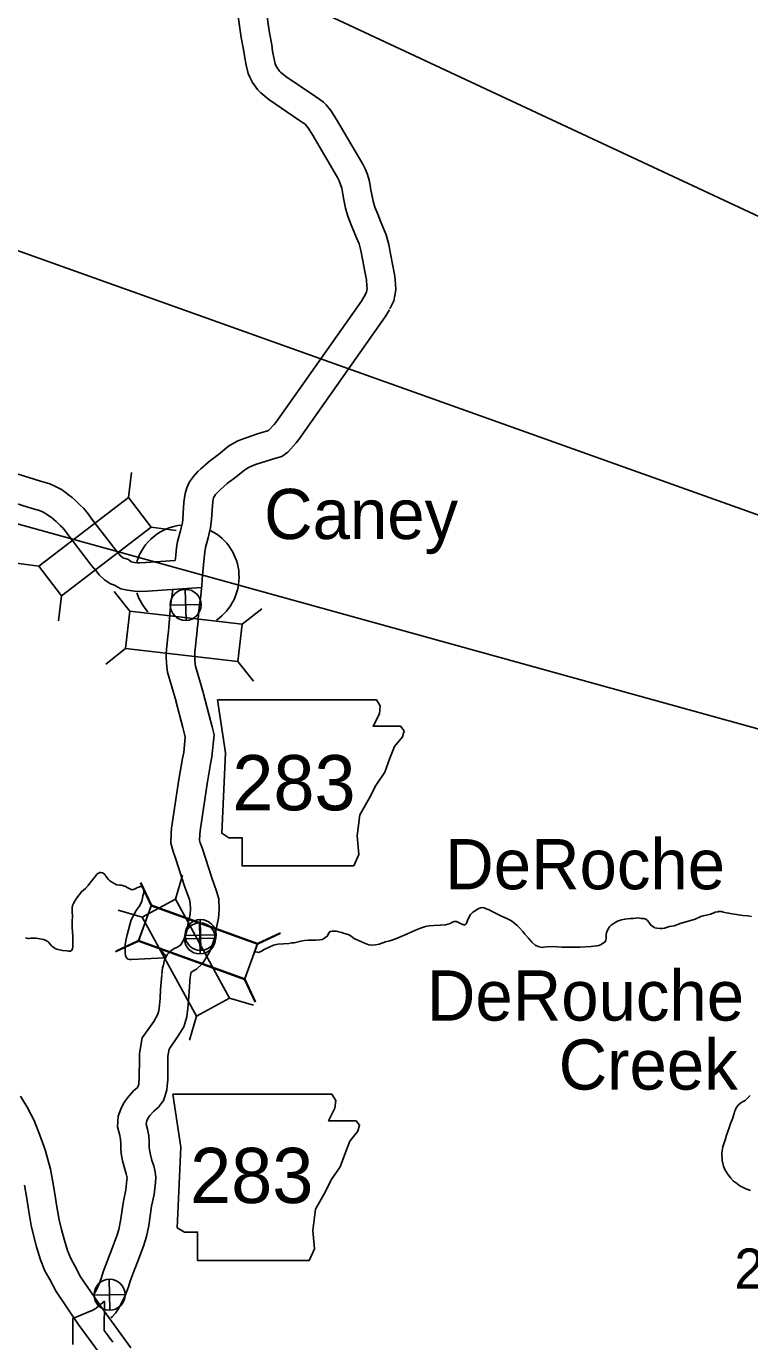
# Model space of a CAD drawing. Extents: x 1373862 to 1377080, y 1164775 to 1170415.
# Drawn here: x 1374281 to 1374357.1, y 1170012.7 to 1170151.1 of the extents above; entities that cross this region are included whole.
import ezdxf

# ---------------------------------------------------------------- set-up
doc = ezdxf.new("R2010")
doc.units = 0
doc.layers.add('1', color=7, linetype='Continuous')
doc.layers.add('Default', color=7, linetype='Continuous')

msp = doc.modelspace()

# ---------------------------------------------------------------- linework, layer by layer
at = {"layer": '1'}
for p in [(1374155.09, 1170226.04), (1374172.84, 1170165.77), (1374199.55, 1170121.07)]:
    msp.add_line(p, (1374640.76, 1169998.76), dxfattribs=at)
at = {"layer": 'Default'}
for p, q in [((1374291.74, 1170101.53), (1374292.08, 1170104.15)), ((1374294.15, 1170098.39), (1374296.77, 1170098.05)), ((1374282.31, 1170094.3), (1374279.7, 1170094.64)), ((1374297.8, 1170088.59), (1374297.72, 1170091.84)), ((1374284.72, 1170091.16), (1374284.38, 1170088.54)), ((1374291.9, 1170089.55), (1374290.26, 1170091.62)), ((1374296.13, 1170090.18), (1374299.39, 1170090.25)), ((1374303.7, 1170088.17), (1374305.77, 1170089.81)), ((1374291.44, 1170085.62), (1374289.37, 1170083.98)), ((1374303.24, 1170084.24), (1374304.88, 1170082.17)), ((1374296.68, 1170059.26), (1374297.42, 1170061.79)), ((1374294.14, 1170058.56), (1374293.02, 1170060.95)), ((1374294.16, 1170058.62), (1374293.04, 1170061.01)), ((1374296.68, 1170059.26), (1374293.2, 1170057.36)), ((1374302.38, 1170048.84), (1374296.68, 1170059.26)), ((1374293.2, 1170057.36), (1374290.67, 1170058.1)), ((1374293.2, 1170057.36), (1374298.9, 1170046.94)), ((1374299.3, 1170053.5), (1374299.23, 1170056.75)), ((1374299.37, 1170053.85), (1374299.29, 1170057.1)), ((1374292.79, 1170054.84), (1374290.4, 1170053.72)), ((1374292.81, 1170054.89), (1374290.42, 1170053.77)), ((1374297.64, 1170055.09), (1374300.89, 1170055.16)), ((1374297.7, 1170055.44), (1374300.96, 1170055.51)), ((1374305.31, 1170054.51), (1374307.7, 1170055.63)), ((1374305.33, 1170054.57), (1374307.72, 1170055.69)), ((1374303.96, 1170050.79), (1374305.08, 1170048.4)), ((1374303.98, 1170050.85), (1374305.1, 1170048.45)), ((1374298.9, 1170046.94), (1374302.38, 1170048.84)), ((1374302.38, 1170048.84), (1374304.91, 1170048.09)), ((1374298.9, 1170046.94), (1374298.16, 1170044.4)), ((1374289.8, 1170016), (1374289.72, 1170019.25)), ((1374288.13, 1170017.59), (1374291.39, 1170017.66))]:
    msp.add_line(p, q, dxfattribs=at)
for points in [[(1374305.59, 1170157.09), (1374306.57, 1170150.41), (1374306.81, 1170149.13), (1374306.9, 1170148.48), (1374307.06, 1170147.64), (1374307.19, 1170147.13), (1374307.25, 1170146.98), (1374307.38, 1170146.71), (1374307.63, 1170146.36), (1374307.72, 1170146.27), (1374308.29, 1170145.8), (1374311.4, 1170143.7), (1374311.86, 1170143.4), (1374312.27, 1170143.11), (1374312.54, 1170142.82), (1374313.03, 1170142.25), (1374313.64, 1170141.29), (1374316.4, 1170136.58), (1374316.67, 1170136.01), (1374316.87, 1170135.49), (1374317.07, 1170134.89), (1374317.18, 1170134.38), (1374317.25, 1170133.87), (1374317.33, 1170133.4), (1374317.49, 1170132.69), (1374317.66, 1170132.07), (1374317.96, 1170131.33), (1374318.25, 1170130.6), (1374318.51, 1170130), (1374318.85, 1170129.14), (1374319.13, 1170128.15), (1374319.3, 1170127.14), (1374319.54, 1170125.89), (1374319.76, 1170124.82), (1374319.82, 1170123.97), (1374319.86, 1170123.36), (1374319.76, 1170122.76), (1374319.64, 1170122.21), (1374319.39, 1170121.64), (1374319.24, 1170121.35)], [(1374302.6, 1170156.79), (1374303.61, 1170149.92), (1374303.85, 1170148.64), (1374303.94, 1170147.99), (1374304.12, 1170146.99), (1374304.34, 1170146.14), (1374304.52, 1170145.73), (1374304.78, 1170145.18), (1374305.3, 1170144.46), (1374305.66, 1170144.08), (1374306.5, 1170143.39), (1374309.75, 1170141.2), (1374310.17, 1170140.92), (1374310.29, 1170140.84), (1374310.32, 1170140.81), (1374310.62, 1170140.46), (1374311.08, 1170139.73), (1374313.74, 1170135.2), (1374313.9, 1170134.84), (1374314.05, 1170134.46), (1374314.18, 1170134.08), (1374314.23, 1170133.85), (1374314.29, 1170133.43), (1374314.38, 1170132.84), (1374314.58, 1170131.95), (1374314.82, 1170131.1), (1374315.17, 1170130.22), (1374315.48, 1170129.44), (1374315.74, 1170128.85), (1374316, 1170128.19), (1374316.2, 1170127.49), (1374316.35, 1170126.6), (1374316.6, 1170125.31), (1374316.78, 1170124.41), (1374316.83, 1170123.77), (1374316.84, 1170123.52), (1374316.81, 1170123.31), (1374316.77, 1170123.13), (1374316.69, 1170122.94), (1374316.59, 1170122.75)], [(1374316.64, 1170122.84), (1374316.24, 1170122.19), (1374310.54, 1170114.07), (1374307.25, 1170109.42), (1374307.08, 1170109.21), (1374306.49, 1170108.55), (1374306.38, 1170108.52), (1374305.32, 1170108.2), (1374304.11, 1170107.79), (1374303.52, 1170107.57), (1374303.17, 1170107.43), (1374302.28, 1170106.9), (1374301.22, 1170106.05), (1374300.23, 1170105.3), (1374299.34, 1170104.52), (1374299.05, 1170104.24), (1374298.57, 1170103.74), (1374298.18, 1170103.16), (1374297.87, 1170102.53), (1374297.72, 1170101.94), (1374297.58, 1170101.03), (1374297.51, 1170099.87), (1374297.46, 1170099.21), (1374297.42, 1170098.9), (1374297.21, 1170098), (1374296.92, 1170096.9), (1374296.79, 1170096.22), (1374296.7, 1170095.11), (1374296.67, 1170094.87)], [(1374319.19, 1170121.26), (1374318.74, 1170120.54), (1374312.99, 1170112.34), (1374309.65, 1170107.61), (1374309.37, 1170107.27), (1374308.5, 1170106.3), (1374307.89, 1170105.83), (1374307.23, 1170105.64), (1374306.23, 1170105.34), (1374305.12, 1170104.97), (1374304.61, 1170104.78), (1374304.5, 1170104.73), (1374303.99, 1170104.43), (1374303.07, 1170103.69), (1374302.13, 1170102.97), (1374301.38, 1170102.32), (1374301.17, 1170102.12), (1374300.91, 1170101.84), (1374300.78, 1170101.66), (1374300.7, 1170101.49), (1374300.66, 1170101.34), (1374300.57, 1170100.72), (1374300.5, 1170099.66), (1374300.45, 1170098.9), (1374300.37, 1170098.36), (1374300.12, 1170097.28), (1374299.85, 1170096.25), (1374299.77, 1170095.81), (1374299.69, 1170094.83)], [(1374296.67, 1170094.87), (1374293.57, 1170094.67), (1374292.9, 1170094.63), (1374292.67, 1170094.65), (1374292.39, 1170094.69), (1374292.21, 1170094.72), (1374292.02, 1170094.76), (1374291.75, 1170094.99), (1374291.16, 1170095.17), (1374291.09, 1170095.22), (1374290.88, 1170095.42), (1374290.6, 1170095.77), (1374290.16, 1170096.27), (1374289.82, 1170096.74), (1374287.91, 1170099.23), (1374287.52, 1170099.8), (1374287.04, 1170100.36), (1374286.68, 1170100.72), (1374286.16, 1170101.21), (1374285.81, 1170101.51), (1374285.45, 1170101.8), (1374285.08, 1170102.07), (1374284.72, 1170102.35), (1374284, 1170102.7), (1374283.47, 1170102.96), (1374282.49, 1170103.24), (1374270.97, 1170106.83)], [(1374299.45, 1170092.04), (1374293.74, 1170091.67), (1374292.86, 1170091.63), (1374292.37, 1170091.67), (1374291.89, 1170091.73), (1374291.63, 1170091.78), (1374290.96, 1170091.9), (1374290.44, 1170092.17), (1374290.29, 1170092.3), (1374289.87, 1170092.43), (1374289.22, 1170092.86), (1374288.67, 1170093.39), (1374288.3, 1170093.84), (1374287.81, 1170094.4), (1374287.42, 1170094.94), (1374285.47, 1170097.47), (1374285.13, 1170097.97), (1374284.83, 1170098.33), (1374284.58, 1170098.58), (1374284.16, 1170098.98), (1374283.9, 1170099.2), (1374283.64, 1170099.4), (1374283.27, 1170099.67), (1374283.1, 1170099.8), (1374282.7, 1170100), (1374282.4, 1170100.14), (1374281.63, 1170100.36), (1374270.05, 1170103.98)], [(1374299.69, 1170094.83), (1374299.53, 1170093.3)], [(1374299.53, 1170093.36), (1374299.47, 1170092.24)], [(1374296.4, 1170091.84), (1374296.24, 1170090.62), (1374296.12, 1170089.65), (1374296.07, 1170088.72), (1374296, 1170087.91), (1374295.94, 1170087.41), (1374295.9, 1170086.93), (1374295.8, 1170086.18), (1374295.74, 1170085.55), (1374295.71, 1170085), (1374295.71, 1170084.6), (1374295.74, 1170084.19), (1374295.79, 1170083.65), (1374295.85, 1170083.15), (1374296.75, 1170080.06)], [(1374299.47, 1170092.24), (1374299.4, 1170091.57), (1374299.34, 1170091.17), (1374299.21, 1170090.23), (1374299.11, 1170089.38), (1374299.06, 1170088.5), (1374298.98, 1170087.63), (1374298.93, 1170087.11), (1374298.88, 1170086.59), (1374298.78, 1170085.83), (1374298.73, 1170085.32), (1374298.71, 1170084.93), (1374298.71, 1170084.71), (1374298.73, 1170084.42), (1374298.77, 1170083.96), (1374298.8, 1170083.76), (1374299.63, 1170080.9)], [(1374300.54, 1170054.38), (1374300.63, 1170054.62), (1374300.8, 1170055.16), (1374300.94, 1170055.95), (1374301.08, 1170056.59), (1374301.2, 1170057.26), (1374301.28, 1170058.16), (1374301.24, 1170059.28), (1374301.01, 1170060.1), (1374300.52, 1170061.48), (1374299.54, 1170064.55), (1374299.3, 1170065.17), (1374299.23, 1170065.46), (1374299.25, 1170066.04), (1374299.27, 1170066.44), (1374300.02, 1170071.38), (1374300.37, 1170073.48), (1374300.53, 1170074.22), (1374300.77, 1170076.55), (1374300.54, 1170077.37), (1374300.37, 1170078.05), (1374299.65, 1170080.85)], [(1374297.59, 1170055.04), (1374297.79, 1170055.59), (1374297.88, 1170055.88), (1374297.99, 1170056.53), (1374298.14, 1170057.18), (1374298.23, 1170057.66), (1374298.28, 1170058.23), (1374298.25, 1170058.81), (1374298.15, 1170059.2), (1374297.68, 1170060.52), (1374296.7, 1170063.57), (1374296.44, 1170064.25), (1374296.21, 1170065.13), (1374296.25, 1170066.17), (1374296.28, 1170066.73), (1374297.05, 1170071.85), (1374297.42, 1170074.04), (1374297.56, 1170074.68), (1374297.72, 1170076.29), (1374297.64, 1170076.6), (1374297.46, 1170077.32), (1374296.74, 1170080.11)], [(1374291.39, 1170054.09), (1374291.41, 1170054.44), (1374291.47, 1170054.89), (1374291.6, 1170055.49), (1374292.02, 1170057.06), (1374292.56, 1170058.06), (1374292.87, 1170058.49), (1374293.05, 1170058.78), (1374293.16, 1170059.04), (1374293.22, 1170059.34), (1374293.26, 1170059.59), (1374293.34, 1170059.78), (1374293.38, 1170060.01), (1374293.37, 1170060.22), (1374293.34, 1170060.31), (1374293.26, 1170060.46), (1374293.17, 1170060.56), (1374293.09, 1170060.59), (1374292.98, 1170060.58), (1374292.83, 1170060.52), (1374292.64, 1170060.44), (1374292.46, 1170060.34), (1374292.14, 1170060.24), (1374292.02, 1170060.27), (1374291.75, 1170060.4), (1374291.36, 1170060.61), (1374290.99, 1170060.71), (1374290.8, 1170060.72), (1374290.54, 1170060.76), (1374290.3, 1170060.87), (1374290.06, 1170061.01), (1374289.96, 1170061.06), (1374289.8, 1170061.18), (1374289.63, 1170061.32), (1374289.51, 1170061.49), (1374289.36, 1170061.68), (1374289.28, 1170061.81), (1374289.22, 1170061.89), (1374289.1, 1170061.98), (1374289.02, 1170062.01), (1374288.95, 1170062.02), (1374288.8, 1170062.04), (1374288.68, 1170062.04), (1374288.62, 1170062), (1374288.53, 1170061.95), (1374288.4, 1170061.84), (1374288.32, 1170061.71), (1374287.78, 1170061.07), (1374287.52, 1170060.7), (1374287.22, 1170060.37), (1374286.8, 1170060.02), (1374286.32, 1170059.4), (1374286.13, 1170059.12), (1374285.95, 1170058.8), (1374285.87, 1170058.57), (1374285.84, 1170058.32), (1374285.82, 1170057.89), (1374285.85, 1170057.48), (1374285.83, 1170056.88), (1374285.83, 1170056.26), (1374285.88, 1170055.35), (1374285.89, 1170055.06), (1374285.89, 1170054.83), (1374285.91, 1170054.58), (1374285.9, 1170054.35), (1374285.89, 1170054.19), (1374285.85, 1170054.05), (1374285.82, 1170053.94), (1374285.77, 1170053.83), (1374285.68, 1170053.77), (1374285.47, 1170053.76), (1374285.28, 1170053.8), (1374284.83, 1170053.84), (1374284.5, 1170053.9), (1374284.2, 1170053.99), (1374284.04, 1170054.06), (1374283.89, 1170054.15), (1374283.69, 1170054.31), (1374283.47, 1170054.56), (1374283.36, 1170054.69), (1374283.28, 1170054.78), (1374283.17, 1170054.84), (1374283.01, 1170054.94), (1374282.81, 1170054.99), (1374282.42, 1170055.08), (1374282.04, 1170055.13), (1374281.69, 1170055.13), (1374281.47, 1170055.13), (1374281.32, 1170055.11), (1374281.2, 1170055.11), (1374281.05, 1170055.13), (1374280.92, 1170055.17)], [(1374356.88, 1170057.5), (1374356.35, 1170057.53), (1374355.7, 1170057.63), (1374355.21, 1170057.71), (1374354.9, 1170057.76), (1374354.59, 1170057.82), (1374354.31, 1170057.89), (1374354.06, 1170057.94), (1374353.93, 1170057.95), (1374353.79, 1170057.95), (1374353.71, 1170057.93), (1374353.45, 1170057.88), (1374353.25, 1170057.79), (1374352.94, 1170057.68), (1374352.55, 1170057.58), (1374352.19, 1170057.48), (1374351.95, 1170057.41), (1374351.33, 1170057.13), (1374350.75, 1170056.96), (1374349.86, 1170056.73), (1374349.13, 1170056.45), (1374348.65, 1170056.36), (1374348.13, 1170056.21), (1374347.86, 1170056.16), (1374347.63, 1170056.16), (1374347.3, 1170056.21), (1374347.11, 1170056.24), (1374347.05, 1170056.27), (1374346.67, 1170056.52), (1374346.46, 1170056.82), (1374346.32, 1170057.01), (1374346.14, 1170057.15), (1374345.95, 1170057.2), (1374345.65, 1170057.23), (1374345.3, 1170057.28), (1374344.81, 1170057.22), (1374344.54, 1170057.22), (1374343.94, 1170057.16), (1374343.6, 1170057.08), (1374343.16, 1170056.92), (1374342.81, 1170056.71), (1374342.5, 1170056.5), (1374342.33, 1170056.34), (1374342.22, 1170056.17), (1374342.1, 1170055.93), (1374342.02, 1170055.72), (1374341.98, 1170055.52), (1374341.97, 1170055.33), (1374341.97, 1170055.14), (1374341.96, 1170054.93), (1374341.88, 1170054.76), (1374341.72, 1170054.64), (1374341.47, 1170054.49), (1374341.22, 1170054.39), (1374340.98, 1170054.32), (1374340.42, 1170054.26), (1374339.25, 1170054.19), (1374338.17, 1170054.18), (1374337.36, 1170054.19), (1374336.3, 1170054.25), (1374335.75, 1170054.23), (1374335.41, 1170054.19), (1374335.27, 1170054.17), (1374334.84, 1170054.26), (1374334.53, 1170054.4), (1374334.15, 1170054.74), (1374333.8, 1170055.16), (1374333.44, 1170055.55), (1374333.22, 1170055.85), (1374332.85, 1170056.27), (1374332.62, 1170056.46), (1374332.43, 1170056.64), (1374332.03, 1170056.98), (1374331.55, 1170057.21), (1374330.98, 1170057.45), (1374330.35, 1170057.79), (1374329.93, 1170057.98), (1374329.67, 1170058.11), (1374329.38, 1170058.22), (1374329.16, 1170058.34), (1374328.95, 1170058.36), (1374328.76, 1170058.32), (1374328.53, 1170058.23), (1374328.12, 1170058), (1374327.91, 1170057.85), (1374327.72, 1170057.63), (1374327.61, 1170057.46), (1374327.53, 1170057.28), (1374327.45, 1170057.11), (1374327.38, 1170056.89), (1374327.27, 1170056.65), (1374327.15, 1170056.56), (1374327.03, 1170056.56), (1374326.8, 1170056.6), (1374326.51, 1170056.75), (1374326.33, 1170056.85), (1374326.23, 1170056.9), (1374326.14, 1170056.9), (1374326.01, 1170056.9), (1374325.83, 1170056.84), (1374325.57, 1170056.7)], [(1374357.26, 1170057.41), (1374356.88, 1170057.5)], [(1374295.26, 1170051.35), (1374295.34, 1170052.04), (1374295.43, 1170052.35), (1374295.51, 1170052.71), (1374295.6, 1170052.98), (1374295.84, 1170053.46), (1374296.21, 1170053.8), (1374296.54, 1170054.05), (1374296.89, 1170054.21), (1374297.16, 1170054.36), (1374297.23, 1170054.42), (1374297.28, 1170054.51), (1374297.58, 1170055.02), (1374297.79, 1170055.59), (1374297.88, 1170055.88), (1374297.99, 1170056.53), (1374298.11, 1170057.06)], [(1374298.24, 1170051.01), (1374298.29, 1170051.44), (1374298.33, 1170051.58), (1374298.9, 1170051.89), (1374299.55, 1170052.47), (1374299.86, 1170052.97), (1374300.31, 1170053.74), (1374300.63, 1170054.62), (1374300.8, 1170055.16), (1374300.94, 1170055.95), (1374300.96, 1170056.04)], [(1374325.57, 1170056.7), (1374325.09, 1170056.56), (1374324.53, 1170056.51), (1374323.85, 1170056.49), (1374323.37, 1170056.45), (1374322.99, 1170056.37), (1374322.46, 1170056.19), (1374321.94, 1170056), (1374320.86, 1170055.48), (1374319.76, 1170055.03), (1374319.22, 1170054.87), (1374318.77, 1170054.77), (1374318.11, 1170054.52), (1374317.72, 1170054.44), (1374317.33, 1170054.41), (1374317.04, 1170054.46), (1374316.49, 1170054.64), (1374315.54, 1170055.06), (1374315.51, 1170055.09), (1374315.15, 1170055.37), (1374314.85, 1170055.52), (1374314.48, 1170055.63), (1374314.15, 1170055.73), (1374313.73, 1170055.85), (1374313.58, 1170055.88), (1374313.17, 1170055.88), (1374313, 1170055.86), (1374312.91, 1170055.82), (1374312.79, 1170055.64), (1374312.73, 1170055.46), (1374312.66, 1170055.35), (1374312.55, 1170055.27), (1374312.37, 1170055.14), (1374312.1, 1170055.01), (1374311.86, 1170054.96), (1374311.43, 1170054.92), (1374310.98, 1170054.93), (1374310.68, 1170054.93), (1374310.27, 1170054.89), (1374309.88, 1170054.83), (1374309.18, 1170054.66), (1374308.94, 1170054.64), (1374308.62, 1170054.6), (1374308.04, 1170054.55), (1374307.47, 1170054.52), (1374306.99, 1170054.41), (1374306.54, 1170054.18), (1374306.01, 1170053.94), (1374305.75, 1170053.78), (1374305.59, 1170053.69), (1374305.43, 1170053.65), (1374305.3, 1170053.66), (1374305.05, 1170053.71)], [(1374295.26, 1170053.85), (1374295.3, 1170053.73), (1374295.35, 1170053.62), (1374295.45, 1170053.49), (1374295.54, 1170053.41), (1374295.64, 1170053.36), (1374295.65, 1170053.28), (1374295.6, 1170053.19), (1374295.53, 1170053.09), (1374292.07, 1170052.9), (1374291.84, 1170052.91), (1374291.71, 1170052.93), (1374291.6, 1170053), (1374291.49, 1170053.14), (1374291.42, 1170053.31), (1374291.39, 1170053.55), (1374291.39, 1170054.09)], [(1374295.25, 1170051.3), (1374295.13, 1170049.74), (1374295.07, 1170048.78), (1374295.01, 1170048.08), (1374294.95, 1170047.51), (1374294.8, 1170047.06), (1374294.4, 1170046.39), (1374293.2, 1170044.65), (1374292.9, 1170043.02), (1374292.89, 1170041.84), (1374292.87, 1170041.03), (1374292.87, 1170040.38), (1374292.83, 1170039.91), (1374292.82, 1170039.77), (1374292.74, 1170039.48), (1374292.71, 1170039.44), (1374292.28, 1170039.08), (1374291.66, 1170038.36), (1374291.43, 1170038.05), (1374291.24, 1170037.75), (1374290.93, 1170037.14), (1374290.68, 1170036.43), (1374290.58, 1170035.3), (1374290.83, 1170034.37), (1374290.91, 1170033.96), (1374290.93, 1170033.58), (1374290.94, 1170033), (1374290.99, 1170032.5), (1374291.11, 1170031.7), (1374291.35, 1170030.85), (1374291.52, 1170030.35), (1374291.59, 1170030.06), (1374291.6, 1170029.91), (1374291.59, 1170029.7), (1374291.48, 1170028.65), (1374291.22, 1170027.48), (1374290.92, 1170025.4), (1374290.75, 1170024.48), (1374290.54, 1170023.82), (1374289.99, 1170022.41), (1374289.54, 1170021.22), (1374289.1, 1170020.04), (1374288.91, 1170019.44), (1374288.65, 1170018.76), (1374288.37, 1170018.13), (1374288.14, 1170017.72), (1374288.08, 1170017.63)], [(1374298.24, 1170051.06), (1374298.12, 1170049.52), (1374298.06, 1170048.57), (1374298, 1170047.79), (1374297.89, 1170046.88), (1374297.56, 1170045.82), (1374296.92, 1170044.76), (1374296.04, 1170043.48), (1374295.9, 1170042.73), (1374295.89, 1170041.79), (1374295.87, 1170040.98), (1374295.87, 1170040.25), (1374295.82, 1170039.62), (1374295.77, 1170039.19), (1374295.61, 1170038.59), (1374295.43, 1170038.07), (1374294.9, 1170037.36), (1374294.4, 1170036.94), (1374294.01, 1170036.49), (1374293.92, 1170036.37), (1374293.85, 1170036.26), (1374293.69, 1170035.95), (1374293.63, 1170035.79), (1374293.62, 1170035.57), (1374293.75, 1170035.05), (1374293.89, 1170034.34), (1374293.93, 1170033.7), (1374293.94, 1170033.16), (1374293.97, 1170032.86), (1374294.05, 1170032.34), (1374294.22, 1170031.74), (1374294.4, 1170031.18), (1374294.55, 1170030.55), (1374294.61, 1170029.95), (1374294.58, 1170029.45), (1374294.45, 1170028.17), (1374294.17, 1170026.94), (1374293.88, 1170024.9), (1374293.66, 1170023.75), (1374293.37, 1170022.83), (1374292.8, 1170021.34), (1374292.35, 1170020.16), (1374291.94, 1170019.06), (1374291.75, 1170018.45), (1374291.42, 1170017.62), (1374291.06, 1170016.8), (1374290.67, 1170016.09), (1374290.37, 1170015.68), (1374290.03, 1170015.31), (1374289.89, 1170015.19)], [(1374280.39, 1170038.52), (1374281.1, 1170037.37), (1374281.84, 1170035.95), (1374282.42, 1170034.41), (1374282.98, 1170032.88), (1374283.56, 1170030.85), (1374283.77, 1170029.67), (1374284.01, 1170028.25), (1374284.23, 1170026.87), (1374284.45, 1170025.52), (1374284.71, 1170024.49), (1374284.98, 1170023.47), (1374285.34, 1170022.27), (1374285.67, 1170021.42), (1374286.09, 1170020.67), (1374286.72, 1170019.52), (1374288.93, 1170016.23), (1374292.01, 1170012.02)], [(1374357.17, 1170028.58), (1374356.68, 1170028.77), (1374356.32, 1170028.93), (1374356.04, 1170029.1), (1374355.68, 1170029.35), (1374355.37, 1170029.57), (1374355.08, 1170029.89), (1374354.74, 1170030.34), (1374354.48, 1170030.8), (1374354.32, 1170031.15), (1374354.28, 1170031.3), (1374354.17, 1170031.74), (1374354.16, 1170032.54), (1374354.26, 1170033.18), (1374354.55, 1170034.03), (1374354.65, 1170034.43), (1374354.92, 1170035.18), (1374355.04, 1170035.55), (1374355.17, 1170035.89), (1374355.28, 1170036.14), (1374355.43, 1170036.69), (1374355.48, 1170036.86), (1374355.55, 1170037.01), (1374355.66, 1170037.29), (1374355.86, 1170037.58), (1374356.15, 1170037.8), (1374356.38, 1170037.94), (1374356.59, 1170038.07), (1374356.85, 1170038.31), (1374357.14, 1170038.6)], [(1374280.82, 1170029.16), (1374281.05, 1170027.76), (1374281.27, 1170026.39), (1374281.51, 1170024.92), (1374281.81, 1170023.74), (1374282.09, 1170022.66), (1374282.5, 1170021.29), (1374282.96, 1170020.13), (1374283.47, 1170019.22), (1374284.15, 1170017.97), (1374286.47, 1170014.51), (1374289.57, 1170010.27)], [(1374289.21, 1170016.93), (1374288.63, 1170016.44), (1374288.35, 1170016.22), (1374288.23, 1170016.13), (1374288.09, 1170016.06), (1374287.98, 1170015.98), (1374287.84, 1170015.92), (1374285.9, 1170015.14), (1374285.88, 1170012.39)], [(1374290.1, 1170012.64), (1374289.62, 1170013.3), (1374289.4, 1170013.59), (1374289.19, 1170013.86), (1374289.21, 1170016.93)]]:
    msp.add_lwpolyline(points, dxfattribs=at)
for points in [[(1374284.72, 1170091.16), (1374294.15, 1170098.39), (1374291.74, 1170101.53), (1374282.31, 1170094.3)], [(1374291.44, 1170085.62), (1374303.24, 1170084.24), (1374303.7, 1170088.17), (1374291.9, 1170089.55)], [(1374301.1, 1170080.23), (1374301.94, 1170074.65), (1374301.56, 1170066.18), (1374302.31, 1170065.71), (1374303.7, 1170065.71), (1374303.7, 1170062.74), (1374315.43, 1170062.74), (1374315.99, 1170063.95), (1374315.8, 1170065.9), (1374316.08, 1170068.13), (1374317.1, 1170069.9), (1374317.76, 1170071.2), (1374318.69, 1170072.6), (1374319.24, 1170074.09), (1374319.71, 1170075.3), (1374320.55, 1170076.32), (1374320.73, 1170076.97), (1374320.36, 1170077.44), (1374317.48, 1170077.44), (1374318.13, 1170078.74), (1374318.22, 1170079.58), (1374317.83, 1170080.22)], [(1374305.33, 1170054.57), (1374294.16, 1170058.62), (1374292.81, 1170054.89), (1374303.98, 1170050.85)], [(1374305.31, 1170054.51), (1374294.14, 1170058.56), (1374292.79, 1170054.84), (1374303.96, 1170050.79)], [(1374296.42, 1170038.73), (1374297.25, 1170033.15), (1374296.88, 1170024.68), (1374297.63, 1170024.21), (1374299.02, 1170024.21), (1374299.02, 1170021.24), (1374310.75, 1170021.24), (1374311.3, 1170022.45), (1374311.12, 1170024.4), (1374311.4, 1170026.63), (1374312.42, 1170028.4), (1374313.07, 1170029.7), (1374314, 1170031.1), (1374314.56, 1170032.59), (1374315.03, 1170033.8), (1374315.86, 1170034.82), (1374316.05, 1170035.47), (1374315.68, 1170035.94), (1374312.79, 1170035.94), (1374313.44, 1170037.24), (1374313.54, 1170038.08), (1374313.15, 1170038.72)]]:
    msp.add_lwpolyline(points, close=True, dxfattribs=at)
for centre in [(1374297.76, 1170090.21), (1374299.26, 1170055.12), (1374299.33, 1170055.48), (1374289.76, 1170017.62)]:
    msp.add_circle(centre, 1.63, dxfattribs=at)
for start, end in [(95.6968, 163.0725), (304.429, 62.4854), (197.5467, 221.8311)]:
    msp.add_arc((1374297.88, 1170093.14), 5.5, start, end, dxfattribs=at)

# ---------------------------------------------------------------- texts
for s, height, p in [('Caney', 5.28, (1374306.01, 1170097.14)), ('283', 5.808, (1374302.67, 1170068.6)), ('DeRoche', 5.28, (1374325.06, 1170060.29)), ('DeRouche', 5.28, (1374323.13, 1170046.47)), ('Creek', 5.28, (1374336.99, 1170039.21)), ('283', 5.808, (1374298.23, 1170027.27)), ('2', 4.22, (1374355.46, 1170018.27))]:
    msp.add_text(s, height=height, dxfattribs=at).set_placement(p)

doc.saveas('drawing.dxf')
